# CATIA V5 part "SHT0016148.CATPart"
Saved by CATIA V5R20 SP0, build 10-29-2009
Part number: SHT0016148
Bounding box of the stored display mesh (mm): x -544.085 to 25.758, y -634 to -591.5, z 0.9 to 104.4
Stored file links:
  C:\Users\hp\Desktop\SHT0016148-宽车主驾驶左侧钣金\SHT0016148.CATPart
  C:\Users\hp\Desktop\SHT0016014-宽车主驾驶底部支架焊接总成\SHT0016014.CATPart
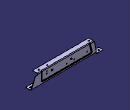
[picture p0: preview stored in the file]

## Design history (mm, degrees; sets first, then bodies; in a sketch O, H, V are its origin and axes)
Body1 (main body)
Body2 "SHT0016149-宽车主驾驶右侧钣金"
  Solid1: solid without history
